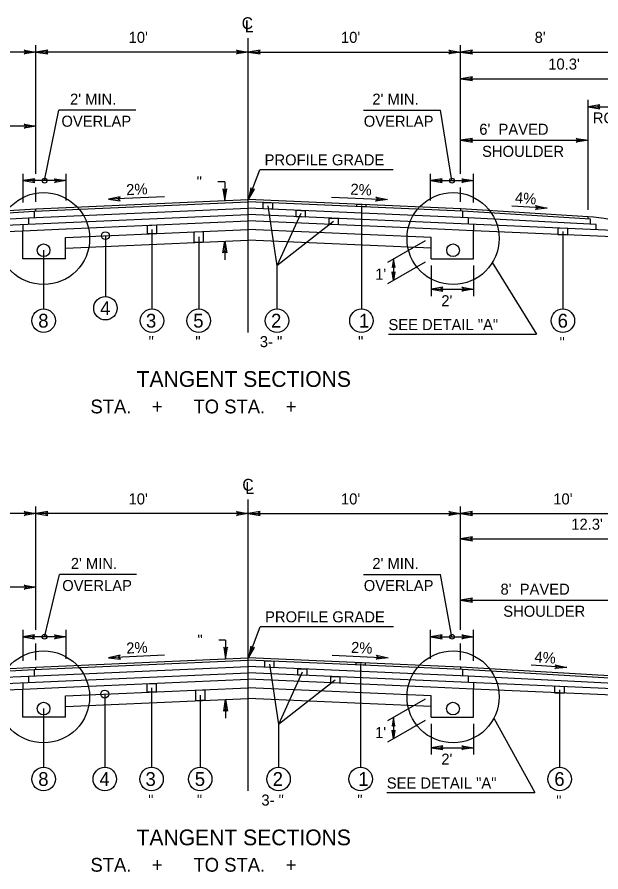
# Model space of a CAD drawing. Extents: x -592 to 1199, y -590 to 416.
# Drawn here: x -355.6 to -281.6, y 44 to 152.4 of the extents above; entities that cross this region are included whole.
import ezdxf

# ---------------------------------------------------------------- set-up
doc = ezdxf.new("R2010")
doc.units = 0
doc.layers.add('1', color=7, linetype='Continuous')
doc.layers.add('Des_ Drain_ Ftrs', color=7, linetype='Continuous')

msp = doc.modelspace()

# ---------------------------------------------------------------- linework, layer by layer
at = {"layer": '1'}
for p, q in [((-326.29, 112.39), (-326.29, 149.72)), ((-353.23, 132.52), (-353.23, 148.84)), ((-299.35, 132.52), (-299.35, 148.84)), ((-353.23, 147.96), (-374.78, 147.96)), ((-326.29, 147.96), (-353.23, 147.96)), ((-326.29, 147.96), (-299.35, 147.96)), ((-299.35, 147.96), (-277.79, 147.96)), ((-299.34, 144.57), (-271.59, 144.57)), ((-283.18, 127.95), (-283.18, 141.88)), ((-283.18, 141), (-272.41, 141)), ((-352.13, 131.64), (-350.33, 140.58)), ((-340.57, 140.58), (-350.33, 140.58)), ((-311.67, 140.58), (-301.91, 140.58)), ((-300.45, 131.64), (-301.91, 140.58)), ((-353.23, 138.56), (-369.38, 138.56)), ((-299.35, 136.76), (-283.18, 136.76)), ((-354.87, 128.86), (-354.87, 132.52)), ((-349.38, 129.13), (-349.38, 132.52)), ((-326.28, 129.25), (-324.84, 133)), ((-307.92, 133), (-324.84, 133)), ((-303.19, 129.13), (-303.19, 132.52)), ((-297.7, 128.86), (-297.7, 132.52)), ((-349.38, 131.64), (-354.87, 131.64)), ((-329.26, 131.5), (-330.14, 131.5)), ((-329.26, 131.5), (-329.26, 129.13)), ((-303.19, 131.64), (-297.7, 131.64)), ((-353.23, 128.96), (-353.23, 130.76)), ((-299.35, 128.96), (-299.35, 130.76)), ((-353.23, 128.08), (-326.29, 129.26)), ((-336.94, 129.59), (-344.03, 129.28)), ((-299.34, 128.08), (-326.29, 129.26)), ((-315.72, 129.55), (-308.64, 129.24)), ((-369.38, 127.06), (-353.23, 128.08)), ((-354.17, 126.93), (-326.29, 128.15)), ((-353.47, 127.77), (-326.29, 128.96)), ((-353.23, 127.78), (-353.23, 128.08)), ((-299.11, 127.77), (-326.29, 128.96)), ((-298.4, 126.93), (-326.29, 128.15)), ((-323.81, 128.44), (-322.65, 120.82)), ((-311.93, 128.47), (-311.93, 115.36)), ((-299.34, 127.78), (-299.34, 128.08)), ((-283.18, 127.07), (-299.34, 128.08)), ((-288.37, 128.15), (-292.86, 128.42)), ((-380.49, 124.97), (-326.29, 127.34)), ((-370.42, 126.1), (-354.17, 126.92)), ((-369.69, 126.74), (-353.47, 127.77)), ((-354.17, 126.91), (-354.17, 126.13)), ((-353.47, 127.76), (-353.47, 126.95)), ((-272.07, 124.97), (-326.29, 127.34)), ((-319.64, 127.46), (-322.65, 120.82)), ((-299.11, 127.77), (-299.11, 126.96)), ((-282.88, 126.75), (-299.11, 127.77)), ((-298.4, 126.93), (-298.4, 126.12)), ((-282.15, 126.1), (-298.4, 126.93)), ((-283.18, 126.77), (-283.18, 127.07)), ((-354.88, 126.1), (-354.88, 125.28)), ((-349.39, 125.52), (-326.29, 126.53)), ((-303.19, 125.52), (-326.29, 126.53)), ((-315.46, 126.45), (-322.65, 120.82)), ((-297.7, 126.09), (-297.7, 125.28)), ((-282.88, 126.13), (-282.88, 126.75)), ((-282.15, 125.41), (-282.15, 126.1)), ((-384.41, 123.99), (-354.88, 125.28)), ((-354.88, 125.28), (-349.39, 125.52)), ((-354.88, 121.74), (-354.88, 125.28)), ((-349.49, 124.44), (-326.29, 125.45)), ((-338.51, 125.46), (-338.51, 115.36)), ((-303.09, 124.44), (-326.29, 125.45)), ((-297.7, 125.28), (-303.19, 125.52)), ((-297.7, 121.74), (-297.7, 125.28)), ((-268.15, 123.99), (-297.7, 125.28)), ((-286.38, 125.19), (-286.38, 115.36)), ((-349.49, 121.74), (-349.49, 124.44)), ((-349.49, 123.09), (-326.29, 124.1)), ((-344.42, 124.66), (-344.42, 116.94)), ((-332.58, 124.51), (-332.58, 115.36)), ((-329.26, 123.98), (-329.26, 121.61)), ((-303.09, 123.09), (-326.29, 124.1)), ((-303.85, 124), (-308.61, 121.25)), ((-303.09, 121.74), (-303.09, 124.44)), ((-303.09, 124.44), (-303.09, 124.44)), ((-352.26, 122.81), (-352.26, 115.36)), ((-349.49, 121.74), (-354.88, 121.74)), ((-307.85, 121.69), (-307.87, 118.99)), ((-303.09, 121.74), (-297.7, 121.74)), ((-322.65, 120.82), (-322.65, 115.36)), ((-303.85, 121.3), (-308.62, 118.55)), ((-303.09, 120.86), (-303.09, 116.98)), ((-297.7, 120.86), (-297.7, 116.98)), ((-295.33, 121.26), (-289.74, 112.18)), ((-303.09, 117.86), (-297.7, 117.86)), ((-308.52, 112.18), (-289.74, 112.18)), ((-326.29, 54.25), (-326.29, 91.18)), ((-353.23, 74.67), (-353.23, 90.3)), ((-299.35, 74.67), (-299.35, 90.3)), ((-353.23, 89.42), (-380.17, 89.42)), ((-326.29, 89.42), (-353.23, 89.42)), ((-326.29, 89.42), (-299.35, 89.42)), ((-299.35, 89.42), (-272.41, 89.42)), ((-299.35, 86.21), (-265.98, 86.21)), ((-352.11, 73.9), (-350.24, 81.68)), ((-340.47, 81.68), (-350.24, 81.68)), ((-311.68, 81.68), (-301.91, 81.68)), ((-300.45, 73.79), (-301.91, 81.68)), ((-353.23, 80.06), (-374.77, 80.06)), ((-299.35, 78.42), (-277.8, 78.42)), ((-326.28, 71.11), (-324.77, 75.03)), ((-307.85, 75.03), (-324.77, 75.03)), ((-349.41, 73.79), (-354.9, 73.79)), ((-354.87, 70.72), (-354.87, 74.67)), ((-349.39, 70.98), (-349.39, 74.67)), ((-303.19, 70.98), (-303.19, 74.67)), ((-303.19, 73.79), (-297.71, 73.79)), ((-297.71, 70.72), (-297.71, 74.67)), ((-353.23, 70.82), (-353.23, 72.91)), ((-329.17, 73.36), (-330.05, 73.36)), ((-329.17, 73.36), (-329.17, 70.99)), ((-299.35, 70.82), (-299.35, 72.91)), ((-353.47, 69.63), (-326.29, 70.81)), ((-353.24, 69.94), (-326.29, 71.11)), ((-336.93, 71.43), (-344.01, 71.12)), ((-299.34, 69.94), (-326.29, 71.11)), ((-299.11, 69.63), (-326.29, 70.81)), ((-315.65, 71.43), (-308.56, 71.12)), ((-375.08, 68.37), (-353.47, 69.63)), ((-374.77, 68.68), (-353.24, 69.94)), ((-354.18, 68.79), (-326.29, 70)), ((-353.47, 69.63), (-353.47, 68.82)), ((-353.24, 69.64), (-353.24, 69.94)), ((-298.4, 68.79), (-326.29, 70)), ((-323.61, 70.29), (-322.45, 62.67)), ((-312.04, 70.34), (-312.04, 57.22)), ((-299.34, 69.64), (-299.34, 69.94)), ((-277.8, 68.68), (-299.34, 69.94)), ((-299.11, 69.63), (-299.11, 68.81)), ((-277.49, 68.36), (-299.11, 69.63)), ((-285.89, 69.9), (-290.38, 70.17)), ((-385.88, 66.59), (-326.29, 69.19)), ((-375.81, 67.72), (-354.17, 68.79)), ((-354.17, 68.79), (-354.17, 67.98)), ((-349.39, 67.38), (-326.29, 68.39)), ((-266.7, 66.59), (-326.29, 69.19)), ((-303.19, 67.38), (-326.29, 68.39)), ((-319.44, 69.31), (-322.45, 62.67)), ((-298.4, 68.79), (-298.4, 67.97)), ((-276.77, 67.72), (-298.4, 68.79)), ((-354.88, 67.95), (-354.88, 67.14)), ((-354.88, 67.14), (-349.39, 67.38)), ((-349.49, 66.29), (-326.29, 67.31)), ((-338.57, 67.31), (-338.57, 57.22)), ((-303.09, 66.29), (-326.29, 67.31)), ((-315.26, 68.29), (-322.45, 62.67)), ((-297.7, 67.14), (-303.19, 67.38)), ((-297.7, 67.95), (-297.7, 67.14)), ((-389.8, 65.61), (-354.88, 67.14)), ((-354.88, 63.6), (-354.88, 67.14)), ((-349.49, 63.6), (-349.49, 66.29)), ((-344.5, 66.51), (-344.5, 57.22)), ((-332.39, 66.37), (-332.39, 57.22)), ((-303.09, 63.6), (-303.09, 66.29)), ((-303.09, 66.29), (-303.09, 66.29)), ((-297.7, 63.6), (-297.7, 67.14)), ((-262.77, 65.61), (-297.7, 67.14)), ((-297.7, 66.99), (-297.7, 66.99)), ((-286.79, 67.06), (-286.79, 57.22)), ((-349.49, 64.95), (-326.29, 65.96)), ((-329.17, 65.84), (-329.17, 63.47)), ((-303.09, 64.95), (-326.29, 65.96)), ((-303.85, 65.85), (-308.61, 63.11)), ((-352.26, 64.67), (-352.26, 57.22)), ((-349.49, 63.6), (-354.88, 63.6)), ((-303.85, 63.16), (-308.63, 60.4)), ((-307.85, 63.55), (-307.87, 60.84)), ((-303.09, 63.6), (-297.7, 63.6)), ((-295.14, 63.45), (-289.94, 54.03)), ((-322.45, 62.67), (-322.45, 57.22)), ((-303.09, 62.72), (-303.09, 58.83)), ((-297.7, 62.72), (-297.7, 58.83)), ((-303.09, 59.71), (-297.7, 59.71)), ((-308.73, 54.03), (-289.94, 54.03))]:
    msp.add_line(p, q, dxfattribs=at)
for points in [[(-324.39, 128.87), (-323.24, 128.82), (-323.24, 128.02), (-324.39, 128.07)], [(-312.51, 128.66), (-311.36, 128.61), (-311.36, 128.31), (-312.51, 128.36)], [(-320.21, 127.88), (-319.06, 127.83), (-319.06, 127.02), (-320.21, 127.07)], [(-316.04, 126.89), (-314.89, 126.84), (-314.89, 126.03), (-316.04, 126.08)], [(-339.09, 125.97), (-337.94, 126.02), (-337.94, 124.94), (-339.09, 124.89)], [(-333.16, 125.15), (-332.01, 125.2), (-332.01, 123.85), (-333.16, 123.8)], [(-285.74, 124.76), (-285.74, 125.57), (-287.02, 125.63), (-287.02, 124.82)], [(-324.18, 70.72), (-323.04, 70.67), (-323.04, 69.86), (-324.18, 69.91)], [(-312.61, 70.52), (-311.47, 70.47), (-311.47, 70.17), (-312.61, 70.22)], [(-320.01, 69.73), (-318.86, 69.68), (-318.86, 68.87), (-320.01, 68.92)], [(-315.83, 68.74), (-314.69, 68.69), (-314.69, 67.88), (-315.83, 67.93)], [(-339.14, 67.82), (-338, 67.87), (-338, 66.8), (-339.14, 66.75)], [(-286.16, 66.63), (-286.16, 67.44), (-287.43, 67.5), (-287.43, 66.68)], [(-332.96, 67.02), (-331.82, 67.07), (-331.82, 65.72), (-332.96, 65.67)]]:
    msp.add_lwpolyline(points, close=True, dxfattribs=at)
for centre, radius in [((-352.13, 131.64), 0.3), ((-300.45, 131.64), 0.3), ((-352.26, 124.3), 5.84), ((-300.31, 124.3), 5.84), ((-344.42, 124.66), 0.5), ((-352.26, 122.81), 0.808), ((-300.31, 122.81), 0.808), ((-344.42, 115.46), 1.49), ((-352.26, 113.88), 1.49), ((-338.51, 113.88), 1.49), ((-332.58, 113.88), 1.49), ((-322.65, 113.88), 1.49), ((-311.93, 113.88), 1.49), ((-286.38, 113.88), 1.49), ((-352.15, 73.79), 0.3), ((-300.45, 73.79), 0.3), ((-352.27, 66.16), 5.84), ((-300.31, 66.16), 5.84), ((-344.5, 66.51), 0.5), ((-352.26, 64.67), 0.808), ((-300.32, 64.67), 0.808), ((-352.26, 55.73), 1.49), ((-344.5, 55.73), 1.49), ((-338.57, 55.73), 1.49), ((-332.39, 55.73), 1.49), ((-322.45, 55.73), 1.49), ((-312.04, 55.73), 1.49), ((-286.79, 55.73), 1.49)]:
    msp.add_circle(centre, radius, dxfattribs=at)
msp.add_arc((-290.07, 60.23), 67.19, 74.7619, 84.1205, dxfattribs=at)
at = {"layer": 'Des_ Drain_ Ftrs'}
for points in [[(-353.23, 147.96), (-354.72, 147.72), (-354.42, 147.96), (-354.72, 148.21)], [(-353.23, 147.96), (-351.74, 147.72), (-352.04, 147.96), (-351.74, 148.21)], [(-326.29, 147.96), (-327.78, 147.72), (-327.48, 147.96), (-327.78, 148.21)], [(-326.29, 147.96), (-324.8, 147.72), (-325.09, 147.96), (-324.8, 148.21)], [(-299.35, 147.96), (-300.84, 147.72), (-300.54, 147.96), (-300.84, 148.21)], [(-299.35, 147.96), (-297.86, 147.72), (-298.15, 147.96), (-297.86, 148.21)], [(-299.34, 144.57), (-297.85, 144.33), (-298.15, 144.57), (-297.85, 144.82)], [(-283.18, 141), (-281.69, 140.75), (-281.99, 141), (-281.69, 141.25)], [(-353.23, 138.56), (-354.72, 138.31), (-354.42, 138.56), (-354.72, 138.8)], [(-299.35, 136.76), (-297.86, 136.51), (-298.15, 136.76), (-297.86, 137.01)], [(-283.18, 136.76), (-284.67, 136.51), (-284.38, 136.76), (-284.67, 137.01)], [(-354.87, 131.64), (-353.38, 131.39), (-353.68, 131.64), (-353.38, 131.89)], [(-349.38, 131.64), (-350.87, 131.39), (-350.58, 131.64), (-350.87, 131.89)], [(-303.19, 131.64), (-301.7, 131.39), (-302, 131.64), (-301.7, 131.89)], [(-297.7, 131.64), (-299.19, 131.39), (-298.9, 131.64), (-299.19, 131.89)], [(-329.26, 129.13), (-329.02, 130.62), (-329.26, 130.32), (-329.51, 130.62)], [(-326.28, 129.25), (-325.51, 130.55), (-325.85, 130.37), (-325.98, 130.73)], [(-344.03, 129.28), (-342.53, 129.09), (-342.83, 129.33), (-342.55, 129.59)], [(-308.64, 129.24), (-310.13, 129.06), (-309.83, 129.29), (-310.11, 129.56)], [(-288.37, 128.15), (-289.87, 127.99), (-289.56, 128.22), (-289.84, 128.48)], [(-329.26, 123.98), (-329.02, 122.49), (-329.26, 122.78), (-329.51, 122.49)], [(-307.85, 121.69), (-308.03, 120.61), (-307.85, 120.82), (-307.67, 120.61)], [(-307.87, 118.99), (-308.04, 120.07), (-307.86, 119.86), (-307.68, 120.07)], [(-303.09, 117.86), (-301.6, 117.61), (-301.89, 117.86), (-301.6, 118.11)], [(-297.7, 117.86), (-299.19, 117.61), (-298.89, 117.86), (-299.19, 118.11)], [(-353.23, 89.42), (-354.72, 89.17), (-354.42, 89.42), (-354.72, 89.67)], [(-353.23, 89.42), (-351.74, 89.17), (-352.04, 89.42), (-351.74, 89.67)], [(-326.29, 89.42), (-327.78, 89.17), (-327.48, 89.42), (-327.78, 89.67)], [(-326.29, 89.42), (-324.8, 89.17), (-325.1, 89.42), (-324.8, 89.67)], [(-299.35, 89.42), (-300.84, 89.17), (-300.54, 89.42), (-300.84, 89.67)], [(-299.35, 89.42), (-297.86, 89.17), (-298.16, 89.42), (-297.86, 89.67)], [(-299.35, 86.21), (-297.86, 85.96), (-298.16, 86.21), (-297.86, 86.46)], [(-353.23, 80.06), (-354.72, 79.81), (-354.42, 80.06), (-354.72, 80.31)], [(-299.35, 78.42), (-297.86, 78.17), (-298.16, 78.42), (-297.86, 78.67)], [(-354.9, 73.79), (-353.41, 73.54), (-353.7, 73.79), (-353.41, 74.04)], [(-349.41, 73.79), (-350.9, 73.54), (-350.6, 73.79), (-350.9, 74.04)], [(-303.19, 73.79), (-301.7, 73.54), (-302, 73.79), (-301.7, 74.04)], [(-297.71, 73.79), (-299.2, 73.54), (-298.9, 73.79), (-299.2, 74.04)], [(-329.17, 70.99), (-328.92, 72.48), (-329.17, 72.18), (-329.41, 72.48)], [(-326.28, 71.11), (-325.52, 72.41), (-325.85, 72.22), (-325.98, 72.59)], [(-344.01, 71.12), (-342.52, 70.94), (-342.82, 71.17), (-342.54, 71.43)], [(-308.56, 71.12), (-310.06, 70.94), (-309.75, 71.17), (-310.04, 71.43)], [(-285.89, 69.9), (-287.39, 69.74), (-287.08, 69.97), (-287.36, 70.24)], [(-329.17, 65.84), (-328.92, 64.35), (-329.17, 64.64), (-329.41, 64.35)], [(-307.85, 63.55), (-308.04, 62.46), (-307.85, 62.68), (-307.68, 62.46)], [(-307.87, 60.84), (-308.04, 61.93), (-307.86, 61.71), (-307.68, 61.92)], [(-303.09, 59.71), (-301.6, 59.47), (-301.9, 59.71), (-301.6, 59.96)], [(-297.7, 59.71), (-299.19, 59.47), (-298.9, 59.71), (-299.19, 59.96)]]:
    msp.add_lwpolyline(points, close=True, dxfattribs=at)

# ---------------------------------------------------------------- texts
at = {"layer": '1'}
for s, height, p in [("10'", 1.4, (-341.47, 149.12)), ("10'", 1.4, (-314.53, 149.12)), ("8'", 1.4, (-289.96, 149.12)), ("10.3'", 1.4, (-288.23, 145.73)), ("2' MIN.", 1.4, (-348.91, 141.28)), ("2' MIN.", 1.4, (-310.55, 141.28)), ('OVERLAP', 1.4, (-350, 138.48)), ('OVERLAP', 1.4, (-311.64, 138.48)), ('ROUNDING', 1.4, (-282.57, 138.9)), ("6'  PAVED", 1.4, (-296.98, 137.46)), ('SHOULDER', 1.4, (-296.63, 134.66)), ('PROFILE GRADE', 1.4, (-324.22, 133.58)), ("2'", 1.4, (-301.8, 115.71)), ('4', 1.75, (-345.09, 114.58)), ('8', 1.75, (-352.94, 113)), ('3', 1.75, (-339.27, 113)), ('5', 1.75, (-333.27, 113)), ('2', 1.75, (-323.4, 113)), ('1', 1.75, (-312.24, 113)), ('SEE DETAIL "A"', 1.4, (-308.51, 112.68)), ('6', 1.75, (-287.04, 113)), (' "', 1.4, (-339.46, 110.52)), (' "', 1.4, (-333.53, 110.52)), ('3- "', 1.4, (-324.83, 110.52)), (' "', 1.4, (-312.88, 110.52)), (' "', 1.4, (-287.32, 110.42)), ('TANGENT SECTIONS', 2, (-340.46, 105.48)), ('STA.    +      TO STA.    +     ', 1.75, (-346.32, 102.12)), ("10'", 1.4, (-341.48, 90.57)), ("10'", 1.4, (-314.53, 90.57)), ("10'", 1.4, (-287.59, 90.57)), ("12.3'", 1.4, (-285.31, 87.36)), ("2' MIN.", 1.4, (-348.81, 82.38)), ("2' MIN.", 1.4, (-310.55, 82.38)), ('OVERLAP', 1.4, (-349.9, 79.58)), ('OVERLAP', 1.4, (-311.64, 79.58)), ("8'  PAVED", 1.4, (-294.29, 79.12)), ('PROFILE GRADE', 1.4, (-324.16, 75.61)), ('SHOULDER', 1.4, (-293.94, 76.32)), ("2'", 1.4, (-301.8, 57.56)), ('8', 1.75, (-352.94, 54.86)), ('4', 1.75, (-345.18, 54.86)), ('3', 1.75, (-339.33, 54.86)), ('5', 1.75, (-333.08, 54.86)), ('2', 1.75, (-323.19, 54.86)), ('1', 1.75, (-312.34, 54.86)), ('6', 1.75, (-287.46, 54.86)), ('SEE DETAIL "A"', 1.4, (-308.72, 54.53)), (' "', 1.4, (-339.51, 52.37)), (' "', 1.4, (-333.33, 52.37)), ('3- "', 1.4, (-324.63, 52.37)), (' "', 1.4, (-312.98, 52.37)), (' "', 1.4, (-287.74, 52.28)), ('TANGENT SECTIONS', 2, (-340.47, 47.33)), ('STA.    +      TO STA.    +     ', 1.75, (-346.32, 43.98))]:
    msp.add_text(s, height=height, dxfattribs=at).set_placement(p)
for s, rotation, p in [('2%', 2.624, (-341.75, 129.79)), ('  "', 0.1438, (-333.88, 130.79)), ('2%', 357.376, (-313.36, 129.87)), ('4%', 356.1875, (-292.49, 128.8)), ("1'", 0.1438, (-310.19, 119.07)), ('  "', 0.1438, (-333.78, 72.65)), ('2%', 2.624, (-341.74, 71.64)), ('2%', 357.376, (-313.28, 71.75)), ('4%', 356.2575, (-290.02, 70.55)), ("1'", 0.1438, (-310.2, 60.93))]:
    msp.add_text(s, height=1.4, rotation=rotation, dxfattribs=at).set_placement(p)
at = {"layer": 'Des_ Drain_ Ftrs'}
for s, p in [('C', (-327.13, 150.87)), ('L', (-326.74, 150.47)), ('C', (-327.05, 92.31)), ('L', (-326.66, 91.91))]:
    msp.add_text(s, height=1.5, dxfattribs=at).set_placement(p)

doc.saveas('drawing.dxf')
